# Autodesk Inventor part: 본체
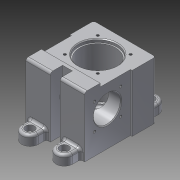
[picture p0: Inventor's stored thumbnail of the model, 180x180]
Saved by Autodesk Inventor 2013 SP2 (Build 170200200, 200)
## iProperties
Created: 2024-11
Part Number: 본체
Material: 알루미늄 6061
Document SubType Name: Modeling
Designer: a
Density: 2.71 g/cm^3
Mass: 807.043 g
Surface Area: 544.935 cm^2
Volume: 297.802 cm^3
Author: a
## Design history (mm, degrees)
sketch "스케치1"
  geometry: L1 (-38, 42.5)-(38, 42.5); L2 (38, 42.5)-(38, -42.5); L3 (38, -42.5)-(-38, -42.5); L4 (-38, -42.5)-(-38, 42.5); L5 (-38, 42.5)-(38, -42.5); L6 (38, 42.5)-(-38, -42.5); 1 further point
  constraints: 12 end point, 2 midpoint, 2 parallel, 1 horizontal, 1 perpendicular
  dimensions: "d0" = 38 distance from line of point (0, 0) L4; "d1" = 85 distance between parallel lines of L3 L1
extrude "돌출1" new body sketch "스케치1" stored distance "d2" = 74; taper "d3" = 0 deg
sketch "스케치2"
  geometry: L1 (-74, 85)-(0, 85) reference; L2 (0, 85)-(-4, 85); L3 (-4, 85)-(-4, 19); L4 (-4, 19)-(0, 19); L5 (0, 19)-(0, 85); 1 further point
  constraints: 8 end point, 2 parallel, 1 horizontal, 1 perpendicular
  dimensions: "d4" = 4 distance between parallel lines of L5 L3; "d6" = 66 distance between parallel lines of L4 L1
extrude "돌출2" cut sketch "스케치2" distance "d7" = 76; taper "d8" = 0 deg
sketch "스케치3"
  geometry: L1 (-38, -23.5)-(-38, -42.5) reference; L2 (-38, -42.5)-(38, -42.5) reference; L3 (38, -42.5)-(38, -23.5) reference; L4 (-38, -42.5)-(-36, -42.5); L5 (-36, -42.5)-(-36, 13.5); L6 (-36, 13.5)-(-38, 13.5); L7 (-38, 13.5)-(-38, -42.5); L8 (38, -42.5)-(36, -42.5); L9 (36, -42.5)-(36, 13.5); L10 (36, 13.5)-(38, 13.5); L11 (38, 13.5)-(38, -42.5); L12 (-6, -27.5)-(6, -27.5); L13 (6, -27.5)-(6, -42.5); L14 (6, -42.5)-(-6, -42.5); L15 (-6, -42.5)-(-6, -27.5); 1 further point
  constraints: 24 end point, 6 parallel, 4 collinear, 3 horizontal, 3 perpendicular, 2 point on line
  dimensions: "d9" = 2 distance between parallel lines of L5 L7; "d11" = 2 distance between parallel lines of L3 L9; "d12" = 56 distance between parallel lines of L2 L6; "d13" = 6 distance from line of point (0, 0) L15; "d14" = 12 distance between parallel lines of L13 L15; "d15" = 15 distance between parallel lines of L12 L2
extrude "돌출3" cut sketch "스케치3" distance "d16" = 76; taper "d17" = 0 deg
sketch "스케치4"
  geometry: L1 (-36, -42.5)-(-6, -42.5) reference; L2 (38, 42.5)-(-38, 42.5) reference; L3 (-21, 62.5)-(-21, 62.5); L4 (-11, 52.5)-(-11, -52.5); L5 (-21, -62.5)-(-21, -62.5); L6 (-31, -52.5)-(-31, 52.5); L7 (21, 62.5)-(21, 62.5); L8 (31, 52.5)-(31, -52.5); L9 (21, -62.5)-(21, -62.5); L10 (11, -52.5)-(11, 52.5); A1 r 10 centre (-21, 52.5) between (-21, 62.5) and (-31, 52.5); A2 r 10 centre (-21, 52.5) between (-11, 52.5) and (-21, 62.5); A3 r 10 centre (21, 52.5) between (21, 62.5) and (11, 52.5); A4 r 10 centre (21, 52.5) between (31, 52.5) and (21, 62.5); A5 r 10 centre (21, -52.5) between (21, -62.5) and (31, -52.5); A6 r 10 centre (21, -52.5) between (11, -52.5) and (21, -62.5); A7 r 10 centre (-21, -52.5) between (-21, -62.5) and (-11, -52.5); A8 r 10 centre (-21, -52.5) between (-31, -52.5) and (-21, -62.5); 1 further point
  constraints: 16 end point, 16 point on circle, 16 tangent, 8 centre point, 7 equal radius, 4 parallel, 2 horizontal, 2 horizontal alignment, 2 perpendicular
  dimensions: "d18" = 20 distance between parallel lines of L4 L6; "d20" = 20 distance between parallel lines of L8 L10; "d21" = 10 radius of A1; "d22" = 21 horizontal distance of A7.centre point (0, 0); "d23" = 42 distance of A5.centre A7.centre; "d24" = 10 distance from line of A7.centre L1; "d25" = 10 distance from line of A1.centre L2
extrude "돌출4" join sketch "스케치4" distance "d26" = 12; taper "d27" = 0 deg
sketch "스케치5"
  geometry: L1 (33, 33)-(33, 29); L2 (33, 29)-(31.5, 29); L3 (31.5, 29)-(31.5, -19); L4 (31.5, -19)-(27, -19); L5 (27, -19)-(27, -30); L6 (27, -30)-(24.5, -30); L7 (24.5, -30)-(24.5, -33); L8 (24.5, -33)-(9.5, -33); L9 (9.5, -33)-(9.5, 33); L10 (9.5, 33)-(33, 33); L11 (42.5, -37)-(42.5, 33) reference; L12 (13.5, 33)-(42.5, 33) reference; L13 (-42.5, 37)-(-27.5, 37) reference; 1 further point
  constraints: 20 end point, 8 parallel, 1 collinear, 1 perpendicular, 1 vertical
  dimensions: "d28" = 33 distance between parallel lines of L9 L11; "d29" = 4 distance between parallel lines of L2 L10; "d30" = 47 diameter of L1 L9; "d31" = 44 diameter of L3 L9; "d32" = 35 diameter of L5 L9; "d33" = 30 diameter of L7 L9; "d34" = 56 distance between parallel lines of L4 L13; "d35" = 11 distance between parallel lines of L6 L4; "d36" = 3 distance between parallel lines of L8 L6
revolve "회전1" sketch "스케치5" stored, may be unused: angle "d37" = 90 deg
sketch "스케치6"
  geometry: L1 (4, 85)-(74, 85) reference; L2 (74, 56)-(74, 0) reference; C1 r 16.5 at (32, 28); 1 further point
  constraints: 1 centre point
  dimensions: "d38" = 57 distance from line of C1.centre L1; "d39" = 33 diameter of C1; "d90" = 42 distance from line of L2 C1.centre
extrude "돌출5" cut sketch "스케치6" distance "d40" = 72; taper "d41" = 0 deg
sketch "스케치7"
  geometry: L1 (2, -66)-(74, -66) reference; L2 (38, -33)-(46.533, -33); L3 (46.533, -33)-(38, -33); L4 (38, -33)-(58.153, -12.847); C1 r 23.5 at (38, -33) reference; 2 further points
  constraints: 6 end point, 1 coincident, 1 collinear, 1 parallel
  dimensions: "d50" = 28.5 distance of L4.end L2.start; "d51" = 45 deg angle of L2 L4
hole "구멍1" sketch "스케치7" at (58.153, -12.847) diameter "d43" = 3.242; stored, may be unused: countersink angle "d47" = 90 deg, drill point angle "d49" = 118 deg; dims "d44" = 8, "d45" = 4, "d46" = 2, "d48" = 10
sketch "스케치8"
  geometry: L1 (-48, 44)-(-16, 44); L2 (-16, 44)-(-16, 12); L3 (-16, 12)-(-48, 12); L4 (-48, 12)-(-48, 44); C1 r 16.5 at (-32, 28) reference; 1 further point
  constraints: 8 end point, 2 parallel, 1 horizontal, 1 perpendicular
  dimensions: "d55" = 16 distance from line of C1.centre L3; "d56" = 32 distance between parallel lines of L1 L3; "d57" = 16 distance from line of L2 C1.centre; "d58" = 32 distance between parallel lines of L4 L2
hole "구멍2" sketch "스케치8" at (-48, 44), (-16, 44), (-16, 12), (-48, 12) diameter "d59" = 3.242; stored, may be unused: countersink angle "d63" = 90 deg, drill point angle "d65" = 118 deg; dims "d60" = 8, "d61" = 4, "d62" = 2, "d64" = 10
sketch "스케치9"
  geometry: L1 (0, 0)-(12, 0) reference; 3 further points
  constraints: 2 vertical alignment
  dimensions: "d66" = 12 distance from line of L1 point (6, -12); "d67" = 40 distance of point (6, -52) point (6, -12)
hole "구멍3" sketch "스케치9" at (6, -12), (6, -52) diameter "d68" = 3.242; stored, may be unused: countersink angle "d72" = 90 deg, drill point angle "d74" = 118 deg; dims "d69" = 8, "d70" = 4, "d71" = 2, "d73" = 10
sketch "스케치10"
  geometry: L1 (-11, 42.5)-(-31, 42.5) reference; L2 (-11, 42.5)-(-11, 52.5) reference; L3 (-31, 52.5)-(-31, 42.5) reference; L4 (31, 42.5)-(11, 42.5) reference; L5 (31, 42.5)-(31, 52.5) reference; L6 (11, 52.5)-(11, 42.5) reference; L7 (11, -42.5)-(31, -42.5) reference; L8 (11, -42.5)-(11, -52.5) reference; L9 (31, -52.5)-(31, -42.5) reference; A1 r 10 centre (-21, -52.5) between (-31, -52.5) and (-11, -52.5) reference; A2 r 10 centre (-21, 52.5) between (-11, 52.5) and (-31, 52.5) reference; A3 r 10 centre (21, 52.5) between (31, 52.5) and (11, 52.5) reference; A4 r 10 centre (21, -52.5) between (11, -52.5) and (31, -52.5) reference; 1 further point
hole "구멍4" sketch "스케치10" at (-21, -52.5), (21, -52.5), (21, 52.5), (-21, 52.5) diameter "d75" = 6.6; stored, may be unused: countersink angle "d79" = 90 deg, drill point angle "d81" = 118 deg; dims "d76" = 8, "d77" = 11, "d78" = 6.6, "d80" = 12
fillet "모깎기2" dims "d86" = 0.6
fillet "모깎기1" dims "d82" = 3
sketch "스케치11"
  geometry: L1 (0, 0)-(70, 0) reference; 2 further points
  constraints: 1 vertical alignment, 1 other
  dimensions: "d83" = 20 distance from line of point (35, 20) L1
feature "엠보싱1" sketch "스케치11" dims "d84" = 0.5, "d85" = 0
chamfer "모따기1" distance "d87" = 1; stored, may be unused: second distance "d88" = 2, angle "d89" = 45 deg
node "솔리드1"
pattern_circular "원형 패턴1" dims angle "d53" = 360 deg
mirror "대칭1"
node "투영된 루프1"
node "투영된 루프2"
node "투영된 루프3"
